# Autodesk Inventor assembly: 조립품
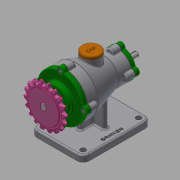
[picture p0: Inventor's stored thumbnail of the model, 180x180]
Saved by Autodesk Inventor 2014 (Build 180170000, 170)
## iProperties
Created: 2020-12
Part Number: 조립품
Document SubType Name: Assembly
Designer: kh
Author: kh
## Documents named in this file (15)
- C:\Users\kh\Desktop\701206V1029\조립품.iam
- C:\Users\kh\Desktop\701206V1029\본체.ipt
- C:\Users\kh\Desktop\701206V1029\마개.ipt
- C:\Users\kh\Desktop\701206V1029\개스킷 A.ipt
- C:\Users\kh\Desktop\701206V1029\스프로킷.ipt
- C:\Users\kh\Desktop\701206V1029\앞커버.ipt
- C:\Users\kh\Desktop\701206V1029\축.ipt
- C:\Users\kh\Desktop\701206V1029\베어링 6203.ipt
- C:\Users\kh\Desktop\701206V1029\오일 실 17 30 8.ipt
- C:\Users\kh\Desktop\701206V1029\키 4x4x14.ipt
- C:\Users\kh\Desktop\701206V1029\개스킷 B.ipt
- C:\Users\kh\Desktop\701206V1029\뒤커버.ipt
- C:\Users\kh\Desktop\701206V1029\베어링 6200.ipt
- C:\Users\kh\Desktop\701206V1029\오일 실 10 20 7.ipt
- C:\Users\kh\Desktop\701206V1029\볼트 M5.ipt
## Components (2 placed, 2 different names)
1. 개스킷 A:1
2. 개스킷 B:1
